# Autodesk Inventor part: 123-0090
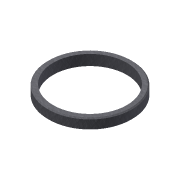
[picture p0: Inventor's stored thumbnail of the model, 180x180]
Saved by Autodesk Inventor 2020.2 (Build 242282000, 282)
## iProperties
Created: 2006-02
Part Number: 123-0090
Document SubType Name: Modeling
Designer: F.Stasiak
Description: Tuleja dystansowa 35x40x5
Material: Stal
Project: Przekładnia X51
Density: 7.85 g/cm^3
Appearance: Stal metaliczna (obrabiana_01)
Manager: www.cadconsulting.pl
Company: Fabian Stasiak CAD Consulting
Author: F.Stasiak
Subject: Zbiór ćwiczeń. Autodesk Inventor 2020. Kurs podstawowy
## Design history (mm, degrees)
sketch "Szkic1"
  geometry: C1 r 17.5 at (0, 0); C2 r 20 at (0, 0); 1 further point
  constraints: 2 centre point, 2 coincident
  dimensions: "d0" = 35 diameter of C1; "d1" = 40 diameter of C2
extrude "Wyciągnięcie proste1" new body sketch "Szkic1" distance "d2" = 5; taper "d3" = 0 deg
chamfer "Faza1" distance "d4" = 0.5; stored, may be unused: second distance "d5" = 2, angle "d6" = 45 deg
node "Bryła1"
node "Korpusy bryłowe"
node "Korpusy powierzchniowe"
